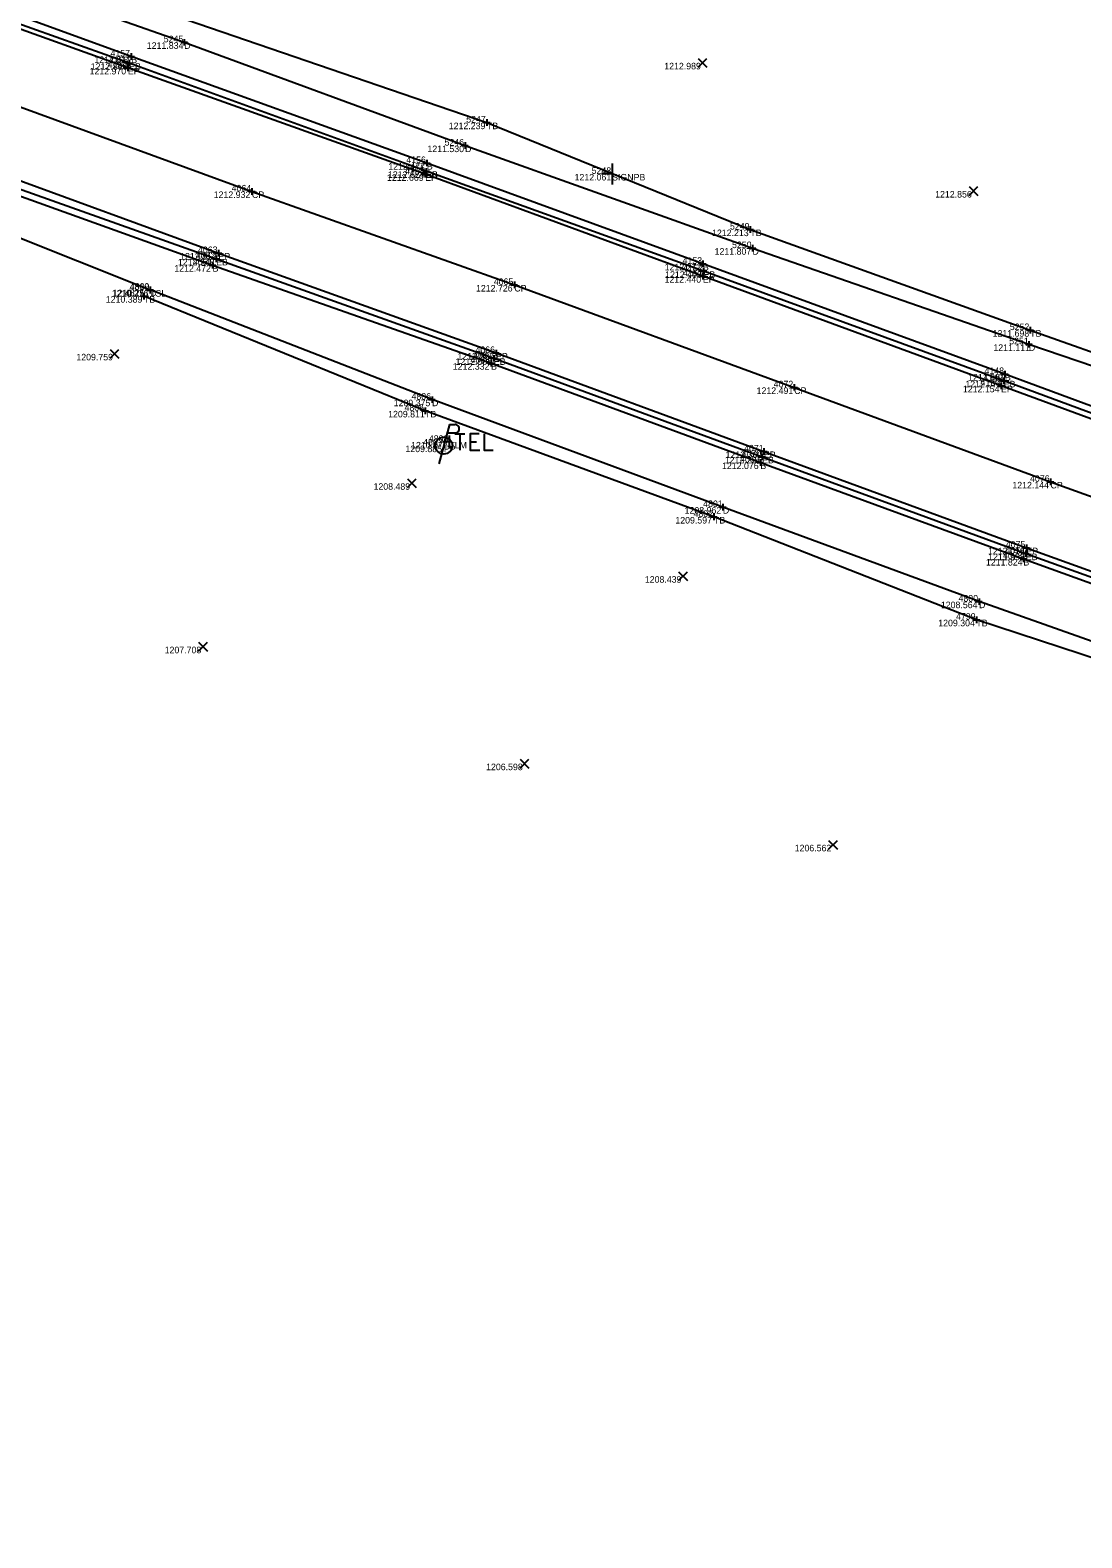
# Model space of a CAD drawing. Extents: x 2044996 to 2050343, y 455232 to 458054.
# Drawn here: x 2048052.2 to 2048212.4, y 456624.4 to 456854.2 of the extents above; entities that cross this region are included whole.
import ezdxf

# ---------------------------------------------------------------- set-up
doc = ezdxf.new("R2010")
doc.units = 0
for name, color, linetype in [('DR_X_Ditch', 7, 'Continuous'), ('DT_X_Contour_Minor', 7, 'Continuous'), ('DT_X_Contour_Text', 7, 'Continuous'), ('DT_X_Spot_Elev', 7, 'Continuous'), ('DT_X_TIN_Hull', 7, 'Continuous'), ('DT_X_Triangles', 7, 'Continuous'), ('DT_X_Void', 7, 'Continuous'), ('PV_X_COP', 7, 'Continuous'), ('PV_X_EOP', 7, 'Continuous'), ('PV_X_Shoulder_Aggregate', 7, 'Continuous'), ('SN_X_Public', 7, 'Continuous'), ('SV_X_Break_Lines', 7, 'Continuous'), ('SV_X_Toe_of_Slope', 7, 'Continuous'), ('SV_X_Top_of_Bank', 7, 'Continuous'), ('UT_X_Electric_Cells', 7, 'Continuous')]:
    doc.layers.add(name, color=color, linetype=linetype)

msp = doc.modelspace()

# ---------------------------------------------------------------- linework, layer by layer
at = {"layer": 'DR_X_Ditch'}
for points in [[(2047780.51, 456960.13), (2047826.93, 456942.06), (2047870.38, 456926.94), (2047917.77, 456909.91), (2047942.94, 456900.89), (2047986.92, 456884.17), (2048032.77, 456867.49), (2048075.71, 456852.37), (2048118.48, 456836.63), (2048162.27, 456821), (2048204.38, 456806.34), (2048252.02, 456790.17), (2048298.22, 456772.41), (2048313.77, 456769.57), (2048332, 456765.35)], [(2048286.21, 456730.57), (2048244.57, 456750.24), (2048196.78, 456767.13), (2048157.76, 456781.54), (2048113.45, 456797.91), (2048070.52, 456814.66)]]:
    msp.add_lwpolyline(points, dxfattribs=at)
at = {"layer": 'DT_X_Spot_Elev'}
for p, q in [((2048153.98, 456848.57), (2048155.31, 456849.91)), ((2048153.98, 456849.91), (2048155.31, 456848.57)), ((2048195.27, 456829.04), (2048196.6, 456830.37)), ((2048195.27, 456830.37), (2048196.6, 456829.04)), ((2048064.42, 456804.22), (2048065.76, 456805.55)), ((2048064.42, 456805.55), (2048065.76, 456804.22)), ((2048109.69, 456784.51), (2048111.02, 456785.84)), ((2048109.69, 456785.84), (2048111.02, 456784.51)), ((2048151.02, 456770.34), (2048152.36, 456771.68)), ((2048151.02, 456771.68), (2048152.36, 456770.34)), ((2048077.89, 456759.59), (2048079.23, 456760.93)), ((2048077.89, 456760.93), (2048079.23, 456759.59)), ((2048126.86, 456741.77), (2048128.2, 456743.1)), ((2048126.86, 456743.1), (2048128.2, 456741.77)), ((2048173.87, 456729.4), (2048175.2, 456730.73)), ((2048173.87, 456730.73), (2048175.2, 456729.4))]:
    msp.add_line(p, q, dxfattribs=at)
at = {"layer": 'DT_X_TIN_Hull'}
for p, q in [((2048116.09, 456790.47), (2048116.09, 456792.47)), ((2048116.09, 456791.47), (2048115.1, 456791.47))]:
    msp.add_line(p, q, dxfattribs=at)
for points in [[(2048116.91, 456792.71), (2048118.46, 456792.71)], [(2048117.7, 456792.71), (2048117.7, 456790.21)], [(2048120.61, 456792.71), (2048119.25, 456792.71), (2048119.25, 456790.21), (2048120.71, 456790.21)], [(2048121.4, 456792.71), (2048121.4, 456790.21), (2048122.75, 456790.21)], [(2048119.25, 456791.47), (2048120.21, 456791.47)]]:
    msp.add_lwpolyline(points, dxfattribs=at)
at = {"layer": 'DT_X_Void'}
for p, q in [((2048075.21, 456852.37), (2048076.21, 456852.37)), ((2048075.71, 456852.87), (2048075.71, 456851.87)), ((2048075.71, 456852.37), (2048075.71, 456852.37)), ((2048066.81, 456849.18), (2048067.81, 456849.18)), ((2048067.13, 456850.21), (2048068.13, 456850.21)), ((2048067.31, 456849.68), (2048067.31, 456848.68)), ((2048067.31, 456849.18), (2048067.31, 456849.18)), ((2048067.63, 456850.71), (2048067.63, 456849.71)), ((2048067.63, 456850.21), (2048067.63, 456850.21)), ((2048066.62, 456848.47), (2048067.62, 456848.47)), ((2048067.12, 456848.97), (2048067.12, 456847.97)), ((2048067.12, 456848.47), (2048067.12, 456848.47)), ((2048121.32, 456840.13), (2048122.32, 456840.13)), ((2048121.82, 456840.63), (2048121.82, 456839.63)), ((2048121.82, 456840.13), (2048121.82, 456840.13)), ((2048117.98, 456836.63), (2048118.98, 456836.63)), ((2048118.48, 456837.13), (2048118.48, 456836.13)), ((2048118.48, 456836.63), (2048118.48, 456836.63)), ((2048112.17, 456833.97), (2048113.17, 456833.97)), ((2048112.55, 456833.21), (2048112.55, 456832.21)), ((2048112.67, 456834.47), (2048112.67, 456833.47)), ((2048112.67, 456833.97), (2048112.67, 456833.97)), ((2048111.91, 456832.25), (2048112.91, 456832.25)), ((2048112.05, 456832.71), (2048113.05, 456832.71)), ((2048112.41, 456832.75), (2048112.41, 456831.75)), ((2048112.41, 456832.25), (2048112.41, 456832.25)), ((2048112.55, 456832.71), (2048112.55, 456832.71)), ((2048085.52, 456829.64), (2048086.52, 456829.64)), ((2048086.02, 456830.14), (2048086.02, 456829.14)), ((2048086.02, 456829.64), (2048086.02, 456829.64)), ((2048161.44, 456823.83), (2048162.44, 456823.83)), ((2048161.94, 456824.33), (2048161.94, 456823.33)), ((2048161.94, 456823.83), (2048161.94, 456823.83)), ((2048162.27, 456821.5), (2048162.27, 456820.5)), ((2048080.07, 456819.36), (2048081.07, 456819.36)), ((2048080.41, 456820.25), (2048081.41, 456820.25)), ((2048080.57, 456819.86), (2048080.57, 456818.86)), ((2048080.57, 456819.36), (2048080.57, 456819.36)), ((2048080.91, 456820.75), (2048080.91, 456819.75)), ((2048080.91, 456820.25), (2048080.91, 456820.25)), ((2048161.77, 456821), (2048162.77, 456821)), ((2048162.27, 456821), (2048162.27, 456821)), ((2048079.52, 456818.41), (2048080.52, 456818.41)), ((2048080.02, 456818.91), (2048080.02, 456817.91)), ((2048080.02, 456818.41), (2048080.02, 456818.41)), ((2048154.22, 456818.61), (2048155.22, 456818.61)), ((2048154.31, 456817.47), (2048155.31, 456817.47)), ((2048154.71, 456817.24), (2048154.71, 456816.24)), ((2048154.72, 456819.11), (2048154.72, 456818.11)), ((2048154.72, 456818.61), (2048154.72, 456818.61)), ((2048154.81, 456817.97), (2048154.81, 456816.97)), ((2048154.81, 456817.47), (2048154.81, 456817.47)), ((2048070, 456814.61), (2048071, 456814.61)), ((2048070.02, 456814.66), (2048071.02, 456814.66)), ((2048070.5, 456815.11), (2048070.5, 456814.11)), ((2048070.5, 456814.61), (2048070.5, 456814.61)), ((2048070.52, 456815.16), (2048070.52, 456814.16)), ((2048070.52, 456814.66), (2048070.52, 456814.66)), ((2048125.49, 456815.39), (2048126.49, 456815.39)), ((2048125.99, 456815.89), (2048125.99, 456814.89)), ((2048125.99, 456815.39), (2048125.99, 456815.39)), ((2048154.21, 456816.74), (2048155.21, 456816.74)), ((2048154.71, 456816.74), (2048154.71, 456816.74)), ((2048069.07, 456813.69), (2048070.07, 456813.69)), ((2048069.57, 456814.19), (2048069.57, 456813.19)), ((2048069.57, 456813.69), (2048069.57, 456813.69)), ((2048204.08, 456808.51), (2048205.08, 456808.51)), ((2048204.58, 456809.01), (2048204.58, 456808.01)), ((2048204.58, 456808.51), (2048204.58, 456808.51)), ((2048123.2, 456805.52), (2048123.2, 456804.52)), ((2048203.88, 456806.34), (2048204.88, 456806.34)), ((2048204.38, 456806.84), (2048204.38, 456805.84)), ((2048204.38, 456806.34), (2048204.38, 456806.34)), ((2048121.95, 456803.47), (2048122.95, 456803.47)), ((2048122.38, 456804.21), (2048123.38, 456804.21)), ((2048122.45, 456803.97), (2048122.45, 456802.97)), ((2048122.45, 456803.47), (2048122.45, 456803.47)), ((2048122.7, 456805.02), (2048123.7, 456805.02)), ((2048122.88, 456804.71), (2048122.88, 456803.71)), ((2048122.88, 456804.21), (2048122.88, 456804.21)), ((2048123.2, 456805.02), (2048123.2, 456805.02)), ((2048200.04, 456800.78), (2048201.04, 456800.78)), ((2048200.23, 456801.81), (2048201.23, 456801.81)), ((2048200.54, 456801.28), (2048200.54, 456800.28)), ((2048200.54, 456800.78), (2048200.54, 456800.78)), ((2048200.73, 456802.31), (2048200.73, 456801.31)), ((2048200.73, 456801.81), (2048200.73, 456801.81)), ((2048168.12, 456799.78), (2048169.12, 456799.78)), ((2048168.62, 456800.28), (2048168.62, 456799.28)), ((2048168.62, 456799.78), (2048168.62, 456799.78)), ((2048199.63, 456800.03), (2048200.63, 456800.03)), ((2048200.13, 456800.53), (2048200.13, 456799.53)), ((2048200.13, 456800.03), (2048200.13, 456800.03)), ((2048111.89, 456796.2), (2048112.89, 456796.2)), ((2048112.39, 456796.7), (2048112.39, 456795.7)), ((2048112.39, 456796.2), (2048112.39, 456796.2)), ((2048112.95, 456797.91), (2048113.95, 456797.91)), ((2048113.45, 456798.41), (2048113.45, 456797.41)), ((2048113.45, 456797.91), (2048113.45, 456797.91)), ((2048163.5, 456790.01), (2048164.5, 456790.01)), ((2048163.75, 456789.71), (2048163.75, 456788.71)), ((2048164, 456790.51), (2048164, 456789.51)), ((2048164, 456790.01), (2048164, 456790.01)), ((2048162.97, 456788.33), (2048163.97, 456788.33)), ((2048163.25, 456789.21), (2048164.25, 456789.21)), ((2048163.47, 456788.83), (2048163.47, 456787.83)), ((2048163.47, 456788.33), (2048163.47, 456788.33)), ((2048163.75, 456789.21), (2048163.75, 456789.21)), ((2048207.17, 456785.38), (2048208.17, 456785.38)), ((2048207.67, 456785.88), (2048207.67, 456784.88)), ((2048207.67, 456785.38), (2048207.67, 456785.38)), ((2048156.4, 456780.53), (2048156.4, 456779.53)), ((2048157.26, 456781.54), (2048158.26, 456781.54)), ((2048157.76, 456782.04), (2048157.76, 456781.04)), ((2048157.76, 456781.54), (2048157.76, 456781.54)), ((2048155.9, 456780.03), (2048156.9, 456780.03)), ((2048156.4, 456780.03), (2048156.4, 456780.03)), ((2048203.99, 456775.85), (2048203.99, 456774.85)), ((2048203.04, 456773.63), (2048204.04, 456773.63)), ((2048203.4, 456774.44), (2048204.4, 456774.44)), ((2048203.49, 456775.35), (2048204.49, 456775.35)), ((2048203.54, 456774.13), (2048203.54, 456773.13)), ((2048203.54, 456773.63), (2048203.54, 456773.63)), ((2048203.9, 456774.94), (2048203.9, 456773.94)), ((2048203.9, 456774.44), (2048203.9, 456774.44)), ((2048203.99, 456775.35), (2048203.99, 456775.35)), ((2048196.28, 456767.13), (2048197.28, 456767.13)), ((2048196.78, 456767.63), (2048196.78, 456766.63)), ((2048196.78, 456767.13), (2048196.78, 456767.13)), ((2048195.88, 456764.37), (2048196.88, 456764.37)), ((2048196.38, 456764.87), (2048196.38, 456763.87)), ((2048196.38, 456764.37), (2048196.38, 456764.37))]:
    msp.add_line(p, q, dxfattribs=at)
at = {"layer": 'PV_X_COP'}
msp.add_lwpolyline([(2047721.58, 456961.45), (2047764.11, 456945.53), (2047805.42, 456930.56), (2047848.07, 456915.19), (2047886.38, 456901.23), (2047928.53, 456886.16), (2047967.24, 456872.35), (2048004.2, 456859.18), (2048043.3, 456845.25), (2048086.02, 456829.64), (2048125.99, 456815.39), (2048168.62, 456799.78), (2048207.67, 456785.38), (2048251.12, 456769.74), (2048292.61, 456754.36), (2048333.81, 456739.22), (2048373.81, 456724.48), (2048417.09, 456709.08), (2048458.61, 456693.82), (2048498.86, 456678.79), (2048537.43, 456664.8), (2048579.13, 456649.5), (2048615.78, 456636.27)], dxfattribs=at)
at = {"layer": 'PV_X_EOP'}
for p, q in [((2048067.12, 456848.47), (2048026.34, 456863.14)), ((2048112.41, 456832.25), (2048067.12, 456848.47)), ((2048040.92, 456834.85), (2048080.91, 456820.25)), ((2048154.71, 456816.74), (2048112.41, 456832.25)), ((2048080.91, 456820.25), (2048123.2, 456805.02)), ((2048200.13, 456800.03), (2048154.71, 456816.74)), ((2048123.2, 456805.02), (2048164, 456790.01)), ((2048243.87, 456783.84), (2048200.13, 456800.03)), ((2048164, 456790.01), (2048203.99, 456775.35)), ((2048203.99, 456775.35), (2048245.85, 456760.2))]:
    msp.add_line(p, q, dxfattribs=at)
at = {"layer": 'PV_X_Shoulder_Aggregate'}
for points in [[(2048620.54, 456647.12), (2048583.12, 456660.67), (2048539.73, 456676.45), (2048498.23, 456691.52), (2048454.17, 456707.97), (2048410.24, 456724.1), (2048369.4, 456738.65), (2048329.21, 456753.43), (2048288.45, 456768.21), (2048244.06, 456784.69), (2048200.54, 456800.78), (2048154.81, 456817.47), (2048112.55, 456832.71), (2048067.31, 456849.18), (2048026.51, 456863.76), (2047982.25, 456879.67), (2047938.09, 456895.41), (2047894.6, 456910.89), (2047855.83, 456924.74), (2047813.34, 456939.9), (2047765.41, 456957.6), (2047718.77, 456974.89)], [(2048040.39, 456833.65), (2048080.57, 456819.36), (2048122.88, 456804.21), (2048163.75, 456789.21), (2048203.9, 456774.44), (2048245.67, 456759.42), (2048288.72, 456743.61), (2048331.35, 456728.01), (2048370.94, 456713.7), (2048413.11, 456698.36), (2048454.57, 456682.93), (2048494.04, 456668.41), (2048534.01, 456653.96), (2048574.84, 456639.09), (2048611.82, 456625.41)]]:
    msp.add_lwpolyline(points, dxfattribs=at)
at = {"layer": 'SN_X_Public'}
for p, q in [((2048140.89, 456833.91), (2048140.89, 456830.71)), ((2048140.89, 456832.31), (2048139.29, 456832.31))]:
    msp.add_line(p, q, dxfattribs=at)
at = {"layer": 'SV_X_Break_Lines'}
for points in [[(2048620.73, 456648.35), (2048583.39, 456661.98), (2048539.9, 456677.65), (2048498.37, 456692.73), (2048454.2, 456708.99), (2048410.48, 456724.96), (2048370.07, 456739.9), (2048329.65, 456754.5), (2048288.87, 456769.18), (2048244.36, 456785.65), (2048200.73, 456801.81), (2048154.72, 456818.61), (2048112.67, 456833.97), (2048067.63, 456850.21), (2048026.62, 456865.12), (2047982.64, 456881.49), (2047938.6, 456897.69), (2047895.04, 456913.55), (2047856.96, 456927.13), (2047813.61, 456942.44), (2047766.63, 456959.74), (2047718.99, 456976.33)], [(2047983.65, 456851.86), (2047998.98, 456847.09), (2048040.01, 456832.79), (2048080.02, 456818.41), (2048122.45, 456803.47), (2048163.47, 456788.33), (2048203.54, 456773.63), (2048245.32, 456758.55), (2048288.48, 456742.77), (2048331.35, 456727.2), (2048370.69, 456712.96), (2048412.95, 456697.59), (2048454.31, 456682.22), (2048493.85, 456667.9), (2048533.48, 456653.1), (2048574.57, 456638.27), (2048611.5, 456624.45)]]:
    msp.add_lwpolyline(points, dxfattribs=at)
at = {"layer": 'SV_X_Toe_of_Slope'}
msp.add_lwpolyline([(2048070.5, 456814.61), (2048026.42, 456832.17), (2047980.02, 456846.58)], dxfattribs=at)
at = {"layer": 'SV_X_Top_of_Bank'}
for points in [[(2047763.11, 456969.57), (2047782.88, 456962.79), (2047830.39, 456947.65), (2047873.41, 456931.98), (2047921.78, 456915.49), (2047944.39, 456907.04), (2047986.44, 456890.77), (2048035.77, 456871.04), (2048076.02, 456855.86), (2048121.82, 456840.13), (2048161.94, 456823.83), (2048204.58, 456808.51), (2048251.96, 456791.72), (2048298.91, 456775.05), (2048316.55, 456773.31), (2048328.45, 456771.26), (2048326.74, 456784.97)], [(2048284.23, 456730.43), (2048244.24, 456748.67), (2048196.38, 456764.37), (2048156.4, 456780.03), (2048112.39, 456796.2), (2048069.57, 456813.69)]]:
    msp.add_lwpolyline(points, dxfattribs=at)
at = {"layer": 'UT_X_Electric_Cells'}
for p, q in [((2048116.11, 456794.11), (2048114.5, 456788.11)), ((2048116.11, 456794.11), (2048116.96, 456794.11)), ((2048115.76, 456792.84), (2048116.96, 456792.84))]:
    msp.add_line(p, q, dxfattribs=at)
msp.add_circle((2048115.25, 456790.91), 1.3, dxfattribs=at)
msp.add_arc((2048116.97, 456793.48), 0.638, 268.8767, 91.1233, dxfattribs=at)

# ---------------------------------------------------------------- texts
at = {"layer": 'DT_X_Contour_Minor'}
for s, p in [('1211.834', (2048070, 456851.37)), ('1212.866', (2048061.47, 456848.18)), ('1212.811', (2048062.01, 456849.21)), ('1212.989', (2048148.83, 456848.24)), ('1212.970', (2048061.28, 456847.47)), ('1212.239', (2048116, 456839.13)), ('1211.530', (2048112.75, 456835.63)), ('1212.477', (2048106.79, 456832.97)), ('1212.669', (2048106.59, 456831.25)), ('1212.624', (2048106.74, 456831.71)), ('1212.061', (2048135.17, 456831.31)), ('1212.932', (2048080.19, 456828.64)), ('1212.856', (2048190.1, 456828.71)), ('1212.213', (2048156.11, 456822.83)), ('1212.748', (2048074.74, 456818.36)), ('1212.812', (2048075.08, 456819.25)), ('1211.807', (2048156.5, 456820)), ('1212.472', (2048074.19, 456817.41)), ('1212.272', (2048148.89, 456817.61)), ('1212.400', (2048148.97, 456816.47)), ('1210.276', (2048064.66, 456813.61)), ('1210.251', (2048064.8, 456813.66)), ('1212.726', (2048120.15, 456814.39)), ('1212.440', (2048148.87, 456815.74)), ('1210.389', (2048063.75, 456812.69)), ('1211.698', (2048198.85, 456807.51)), ('1211.111', (2048198.97, 456805.34)), ('1209.759', (2048059.27, 456803.89)), ('1212.332', (2048116.62, 456802.47)), ('1212.506', (2048117.04, 456803.21)), ('1212.587', (2048117.32, 456804.02)), ('1212.078', (2048194.7, 456799.78)), ('1211.961', (2048195.12, 456800.81)), ('1212.491', (2048162.9, 456798.78)), ('1212.154', (2048194.32, 456799.03)), ('1209.811', (2048106.77, 456795.2)), ('1209.375', (2048107.61, 456796.91)), ('1209.885', (2048109.4, 456789.91)), ('1210.072', (2048110.26, 456790.47)), ('1212.360', (2048158.17, 456789.01)), ('1212.076', (2048157.63, 456787.33)), ('1212.251', (2048158.04, 456788.21)), ('1208.489', (2048104.54, 456784.17)), ('1212.144', (2048201.86, 456784.38)), ('1208.962', (2048151.93, 456780.54)), ('1209.597', (2048150.52, 456779.03)), ('1211.824', (2048197.83, 456772.63)), ('1212.016', (2048198.15, 456774.35)), ('1211.993', (2048198.17, 456773.44)), ('1208.439', (2048145.87, 456770.01)), ('1208.564', (2048190.97, 456766.13)), ('1209.304', (2048190.57, 456763.37)), ('1207.708', (2048072.72, 456759.26)), ('1206.598', (2048121.69, 456741.44)), ('1206.562', (2048168.7, 456729.07))]:
    msp.add_text(s, height=1, dxfattribs=at).set_placement(p)
at = {"layer": 'DT_X_Contour_Text'}
for s, p in [('D', (2048075.71, 456851.37)), ('EB', (2048067.31, 456848.18)), ('B', (2048067.63, 456849.21)), ('EP', (2048067.12, 456847.47)), ('TB', (2048121.82, 456839.13)), ('D', (2048118.48, 456835.63)), ('B', (2048112.67, 456832.97)), ('EP', (2048112.41, 456831.25)), ('EB', (2048112.55, 456831.71)), ('SIGNPB', (2048140.89, 456831.31)), ('CP', (2048086.02, 456828.64)), ('TB', (2048161.94, 456822.83)), ('EB', (2048080.57, 456818.36)), ('EP', (2048080.91, 456819.25)), ('D', (2048162.27, 456820)), ('B', (2048080.02, 456817.41)), ('B', (2048154.72, 456817.61)), ('EB', (2048154.81, 456816.47)), ('TSL', (2048070.5, 456813.61)), ('D', (2048070.52, 456813.66)), ('CP', (2048125.99, 456814.39)), ('EP', (2048154.71, 456815.74)), ('TB', (2048069.57, 456812.69)), ('TB', (2048204.58, 456807.51)), ('D', (2048204.38, 456805.34)), ('B', (2048122.45, 456802.47)), ('EB', (2048122.88, 456803.21)), ('EP', (2048123.2, 456804.02)), ('EB', (2048200.54, 456799.78)), ('B', (2048200.73, 456800.81)), ('CP', (2048168.62, 456798.78)), ('EP', (2048200.13, 456799.03)), ('TB', (2048112.39, 456795.2)), ('D', (2048113.45, 456796.91)), ('PP', (2048115.25, 456789.91)), ('TLM', (2048116.09, 456790.47)), ('EP', (2048164, 456789.01)), ('B', (2048163.47, 456787.33)), ('EB', (2048163.75, 456788.21)), ('CP', (2048207.67, 456784.38)), ('D', (2048157.76, 456780.54)), ('TB', (2048156.4, 456779.03)), ('B', (2048203.54, 456772.63)), ('EB', (2048203.9, 456773.44)), ('EP', (2048203.99, 456774.35)), ('D', (2048196.78, 456766.13)), ('TB', (2048196.38, 456763.37))]:
    msp.add_text(s, height=1, dxfattribs=at).set_placement(p)
at = {"layer": 'DT_X_Triangles'}
for s, p in [('5245', (2048072.58, 456852.37)), ('4159', (2048064.02, 456848.47)), ('4158', (2048064.2, 456849.18)), ('4157', (2048064.47, 456850.21)), ('5247', (2048118.66, 456840.13)), ('5246', (2048115.36, 456836.63)), ('4154', (2048109.32, 456832.25)), ('4155', (2048109.42, 456832.71)), ('4156', (2048109.54, 456833.97)), ('5248', (2048137.77, 456832.31)), ('4064', (2048082.93, 456829.64)), ('5249', (2048158.84, 456823.83)), ('5250', (2048159.15, 456821)), ('4061', (2048077.02, 456818.41)), ('4062', (2048077.46, 456819.36)), ('4063', (2048077.8, 456820.25)), ('4153', (2048151.62, 456818.61)), ('4152', (2048151.7, 456817.47)), ('4151', (2048151.71, 456816.74)), ('4811', (2048066.67, 456813.69)), ('4810', (2048067.38, 456814.61)), ('4809', (2048067.42, 456814.66)), ('4065', (2048122.86, 456815.39)), ('5252', (2048201.47, 456808.51)), ('4066', (2048120.07, 456805.02)), ('5251', (2048201.38, 456806.34)), ('4068', (2048119.33, 456803.47)), ('4067', (2048119.72, 456804.21)), ('4072', (2048165.5, 456799.78)), ('4150', (2048197.01, 456800.03)), ('4149', (2048197.44, 456800.78)), ('4148', (2048197.62, 456801.81)), ('4806', (2048110.33, 456797.91)), ('4805', (2048109.26, 456796.2)), ('4807', (2048112.09, 456790.91)), ('4808', (2048112.97, 456791.47)), ('4069', (2048160.37, 456788.33)), ('4070', (2048160.63, 456789.21)), ('4071', (2048161, 456790.01)), ('4076', (2048204.55, 456785.38)), ('4801', (2048154.76, 456781.54)), ('4802', (2048153.28, 456780.03)), ('4074', (2048200.81, 456774.44)), ('4075', (2048200.86, 456775.35)), ('4073', (2048200.43, 456773.63)), ('4800', (2048193.66, 456767.13)), ('4799', (2048193.28, 456764.37))]:
    msp.add_text(s, height=1, dxfattribs=at).set_placement(p)

doc.saveas('drawing.dxf')
